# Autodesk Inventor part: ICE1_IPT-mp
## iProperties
Created: 2006-11
Part Number: ICE1_IPT-mp
Document SubType Name: Blech
Designer: A.Hombrecher
Material: Edelstahl, austenitisch
Description: ICE1 Weihnachtsgeschenk
AIMD_ORIGIN: ICE1
Author: A.Hombrecher
Title: ICE1 Weihnachtsgeschenk
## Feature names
1. Spiegeln1 [Mirror]
2. Biegung7
3. Grobblech3
4. Grobblech6
5. Biegung3
6. Grobblech8
7. Biegung5
8. Grobblech9
9. Biegung8
10. Ausklinkung1
